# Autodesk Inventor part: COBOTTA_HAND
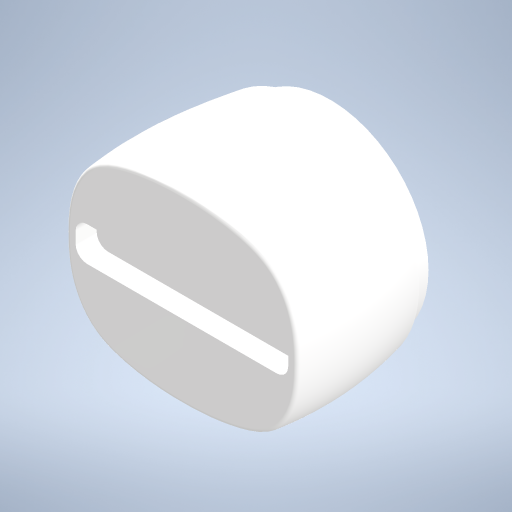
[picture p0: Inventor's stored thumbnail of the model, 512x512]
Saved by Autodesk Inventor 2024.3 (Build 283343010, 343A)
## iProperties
Created: 2020-04
Part Number: COBOTTA_HAND
Material: 一般
Description: NOT SPECIFIED
Document SubType Name: Modeling
Designer: kouki
Density: 1 g/cm^3
Appearance: 既定
Author: kouki
Revision Number: 1LAST_VERSION
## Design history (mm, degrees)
feature "Base1"
node "ソリッド1"
